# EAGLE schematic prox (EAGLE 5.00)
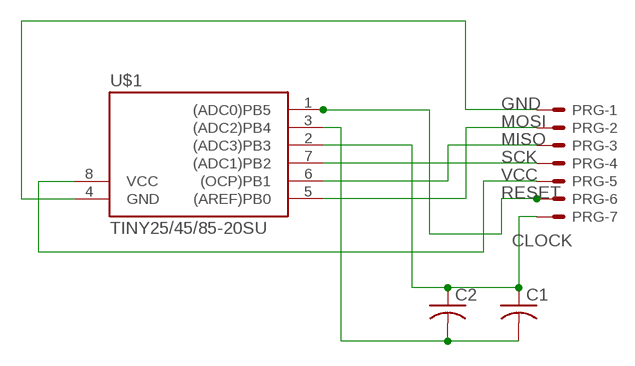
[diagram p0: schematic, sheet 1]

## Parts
C1  C-USC0603  [C0603]
C2  C-USC0603  [C0603]
PRG  22-23-2071  [22-23-2071]
U$1  TINY25/45/85-20SU  [SOIC8]

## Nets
CLOCK: C1.1 C2.1 PRG.7 U$1.2((ADC3)PB3)
GND: PRG.1 U$1.4(GND)
MISO: PRG.3 U$1.6((OCP)PB1)
MOSI: PRG.2 U$1.5((AREF)PB0)
N$8: C1.2 C2.2 U$1.3((ADC2)PB4)
RESET: PRG.6 U$1.1((ADC0)PB5)
SCK: PRG.4 U$1.7((ADC1)PB2)
VCC: PRG.5 U$1.8(VCC)

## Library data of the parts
C1 C2 = rcl:C-US: CAPACITOR, American symbol
PRG = con-molex:22-23-2071: .100" (2.54mm) Center Header - 7 Pin
U$1 = avr-7:TINY25/45/85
